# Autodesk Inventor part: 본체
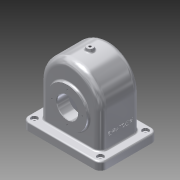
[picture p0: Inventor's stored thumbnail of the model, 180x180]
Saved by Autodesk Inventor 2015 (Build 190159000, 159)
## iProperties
Created: 2016-10
Part Number: 본체
Material: 알루미늄 6061
Document SubType Name: Modeling
Designer: pc01
Density: 2.7 g/cm^3
Appearance: 알루미늄 - 평지
Mass: 1143.78 g
Surface Area: 1196.99 cm^2
Volume: 423.621 cm^3
Author: pc01
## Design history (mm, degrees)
sketch "스케치1"
  geometry: L1 (-58, 80)-(58, 80); L2 (58, 80)-(58, 0); L3 (58, 0)-(-58, 0); L4 (-58, 0)-(-58, 80); C1 r 58 at (0, 80); 2 further points
  constraints: 8 end point, 2 parallel, 1 centre point, 1 coincident, 1 horizontal, 1 midpoint, 1 perpendicular, 1 vertical alignment
  dimensions: "d0" = 80 distance from line of L1 point (0, 0); "d1" = 116 distance of L1.start L1.end; "d2" = 80 distance of L3.end L1.start; "d3" = 116 diameter of C1
extrude "돌출1" new body sketch "스케치1" stored distance "d4" = 77; taper "d5" = 0 deg
sketch "스케치2"
  geometry: L1 (-17, 16.5)-(133, 16.5); L2 (133, 16.5)-(133, -93.5); L3 (133, -93.5)-(-17, -93.5); L4 (-17, -93.5)-(-17, 16.5); 1 further point
  constraints: 8 end point, 2 parallel, 1 horizontal, 1 perpendicular
  dimensions: "d6" = 150 distance of L1.start L1.end; "d7" = 110 distance of L1.end L2.end; "d8" = 55 distance from line of point (58, -38.5) L1; "d9" = 75 distance from line of point (58, -38.5) L4
extrude "돌출2" join sketch "스케치2" distance "d10" = 15; taper "d11" = 0 deg
fillet "모깎기1" dims "d12" = 13
sketch "스케치3"
  geometry: L1 (0, -55)-(0, 55) reference; L2 (80, 33.5)-(0, 33.5); L3 (0, 33.5)-(0, -33.5); L4 (0, -33.5)-(80, -33.5); L5 (80, -33.5)-(80, 33.5); 1 further point
  constraints: 8 end point, 2 midpoint, 2 parallel, 1 horizontal, 1 perpendicular
  dimensions: "d21" = 67 distance of L2.end L3.end; "d22" = 80 distance between parallel lines of L1 L5
extrude "돌출3" cut sketch "스케치3" stored distance "d23" = 104; taper "d24" = 0 deg
sketch "스케치4"
  geometry: L1 (-52, 80)-(52, 80) reference; C1 r 52 at (0, 80); 2 further points
  constraints: 1 centre point, 1 coincident, 1 midpoint
  dimensions: "d25" = 104 diameter of C1
extrude "돌출4" cut sketch "스케치4" stored distance "d26" = 67; taper "d27" = 0 deg
sketch "스케치6"
  geometry: L1 (-75, 0)-(75, 0) reference; C1 r 37.5 at (0, 65); 2 further points
  constraints: 1 centre point, 1 midpoint, 1 vertical alignment
  dimensions: "d35" = 75 diameter of C1; "d36" = 65 distance of point (0, 0) C1.centre
extrude "돌출5" join sketch "스케치6" distance "d37" = 5; taper "d38" = 0 deg
node "작업 평면1"
sketch "스케치7"
  geometry: L1 (-75, 0)-(75, 0) reference; C1 r 31 at (0, 65); 2 further points
  constraints: 1 centre point, 1 midpoint, 1 vertical alignment
  dimensions: "d40" = 62 diameter of C1; "d41" = 65 distance from line of L1 C1.centre
extrude "돌출6" join sketch "스케치7" stored distance "d42" = 5; taper "d43" = 0 deg
sketch "스케치8"
  geometry: C1 r 37.5 at (0, 0) reference; C2 r 20 at (0, 0); 1 further point
  constraints: 1 centre point, 1 coincident
  dimensions: "d44" = 40 diameter of C2
extrude "돌출7" cut sketch "스케치8" stored distance "d45" = 24; taper "d46" = 0 deg
sketch "스케치9"
  geometry: L1 (65, 21.247)-(65, 33.5); L2 (65, 33.5)-(103.281, 33.5); L3 (103.281, 33.5)-(93, 21.247); L4 (93, 21.247)-(65, 21.247)
  constraints: 8 end point, 2 horizontal
  dimensions: "d57" = 50 deg angle of L3 L4; "d58" = 56 diameter of L3.end L1
revolve "회전1" sketch "스케치9" stored, may be unused: angle "d60" = 90 deg
fillet "모깎기2" dims "d61" = 8
sketch "스케치13" dims "d80" = 58
  geometry: C1 r 37.5 at (0, 0) reference; 3 further points
  constraints: 2 vertical alignment, 1 coincident, 2 other
hole "구멍2" sketch "스케치13" at (0, 29) diameter "d81" = 2.459; stored, may be unused: countersink angle "d85" = 90 deg, drill point angle "d87" = 118 deg; dims "d82" = 6, "d83" = 4, "d84" = 2, "d86" = 8
sketch "스케치14" dims "d91" = 52
  geometry: C1 r 31 at (0, 0) reference; 3 further points
  constraints: 2 vertical alignment, 1 coincident, 2 other
hole "구멍3" sketch "스케치14" at (0, 26) diameter "d92" = 2.459; stored, may be unused: countersink angle "d96" = 90 deg, drill point angle "d98" = 118 deg; dims "d93" = 6, "d94" = 4, "d95" = 2, "d97" = 8
fillet "모깎기3" dims "d102" = 12
sketch "스케치15"
  geometry: L1 (-5, -16.5)-(121, -16.5) reference; L2 (133, -4.5)-(133, 81.5) reference; L3 (121, 93.5)-(-5, 93.5) reference; L4 (-17, 81.5)-(-17, -4.5) reference; L5 (103, 77)-(13, 77) reference; L6 (116, 13)-(116, 64) reference; L7 (13, 0)-(103, 0) reference; L8 (0, 64)-(0, 13) reference; A1 r 12 centre (-5, -4.5) between (-17, -4.5) and (-5, -16.5) reference; A2 r 12 centre (121, -4.5) between (121, -16.5) and (133, -4.5) reference; A3 r 12 centre (121, 81.5) between (133, 81.5) and (121, 93.5) reference; A4 r 12 centre (-5, 81.5) between (-5, 93.5) and (-17, 81.5) reference; A5 r 13 centre (103, 64) between (116, 64) and (103, 77) reference; A6 r 13 centre (103, 13) between (103, 0) and (116, 13) reference; A7 r 13 centre (13, 13) between (0, 13) and (13, 0) reference; A8 r 13 centre (13, 64) between (13, 77) and (0, 64) reference; 1 further point
hole "구멍4" sketch "스케치15" at (121, 81.5), (-5, 81.5), (-5, -4.5), (121, -4.5) diameter "d103" = 5; stored, may be unused: countersink angle "d107" = 90 deg, drill point angle "d109" = 0 deg; dims "d104" = 6, "d105" = 12, "d106" = 5, "d108" = 8
fillet "모깎기4" dims "d110" = 3
sketch "스케치16"
  geometry: C1 r 20 at (0, 0) reference; 1 further point
extrude "돌출9" cut sketch "스케치16" stored distance "d111" = 24; taper "d112" = 0 deg
sketch "스케치17"
  geometry: L1 (4.5, 80)-(4.5, 15) reference; 2 further points
  constraints: 1 other
  dimensions: "d113" = 40 distance of point (43, 0) point (43, 40); "d114" = 38.5 distance from line of L1 point (43, 40)
feature "엠보싱1" sketch "스케치17" dims "d0" = 80, "d1" = 116, "d2" = 80, "d3" = 116, "d115" = 0.5, "d116" = 0
fillet "모깎기5" dims "d117" = 3
sketch "스케치18"
  geometry: L1 (134, 0)-(144, 0); L2 (144, 0)-(144, 6); L3 (144, 6)-(134, 7.763); L4 (134, 7.763)-(134, 0); L5 (124, 33.5)-(80, 33.5) reference; 1 further point
  constraints: 8 end point, 2 perpendicular, 1 horizontal
  dimensions: "d118" = 33.5 distance from line of L5 L1.end; "d119" = 12 diameter of L2.end L1; "d120" = 100 deg angle of L4 L3; "d121" = 144 distance of point (0, 0) L1.end; "d122" = 10 distance of L1.start L1.end
revolve "회전2" sketch "스케치18" stored, may be unused: angle "d123" = 90 deg
sketch "스케치19"
  geometry: C1 r 6 at (0, 0) reference; 1 further point
hole "구멍5" sketch "스케치19" at (0, 0) diameter "d124" = 4.459; stored, may be unused: countersink angle "d128" = 90 deg, drill point angle "d130" = 118 deg; dims "d125" = 100, "d126" = 4, "d127" = 2, "d129" = 12.8
fillet "모깎기6" dims "d131" = 3
chamfer "모따기1" distance "d132" = 1; stored, may be unused: second distance "d133" = 2, angle "d134" = 45 deg
chamfer "모따기2" distance "d135" = 1; stored, may be unused: second distance "d136" = 2, angle "d137" = 45 deg
node "솔리드1"
pattern_circular "원형 패턴1" dims angle "d89" = 360 deg
pattern_circular "원형 패턴2" dims angle "d100" = 360 deg
node "투영된 루프2"
node "투영된 루프3"
node "투영된 루프4"
other parameters: "d39" = -87
